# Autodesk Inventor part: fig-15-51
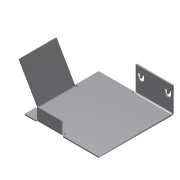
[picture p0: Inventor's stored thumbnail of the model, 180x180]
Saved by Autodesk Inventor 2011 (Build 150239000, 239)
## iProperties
Shininess: 77.0
Angle Display Precision: 2
Document Length Units: 11269
Document Angle Units: 11279
Document Time Units: 11290
Document Mass Units: 11283
Document Length Units Precision: 3
Document Angle Units Precision: 2
Created: 2002-04
Part Number: fig-15-51
Document SubType Name: Sheet Metal
Density: 1 g/cm^3
Sheet Metal Rule: Default
Density: 0.0
Volumn: 0.0
Area: 0.0
PropertySet Name: Model Information
Control State: 0
Master: False
Checked Out: False
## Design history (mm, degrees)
node "Face1"
  sketch "Sketch1"
    geometry: L1 (12.647, 25.882)-(12.647, -14.118); L2 (12.647, -14.118)-(-17.353, -14.118); L3 (-17.353, -14.118)-(-17.353, 15.882); L4 (-17.353, 15.882)-(-2.353, 15.882); L5 (-2.353, 15.882)-(-2.353, 25.882); L6 (-2.353, 25.882)-(12.647, 25.882); 1 further point
    constraints: 12 end point, 4 parallel, 1 perpendicular
    dimensions: "d5" = 30 distance of L2.end L3.end; "d6" = 10 distance of L4.end L5.end; "d7" = 15 distance of L3.end L4.end; "d25" = 15 distance of L5.end L1.start
sketch "Sketch3"
  geometry: L1 (10, -15)-(10, 0)
  constraints: 2 end point
feature "Fold3" sketch "Sketch3" dims "d26" = 0.5 (= BendRadius), "d27" = 90 deg, "d28" = 0.5 (= BendRadius), "d96" = 0.5 (= BendReliefWidth), "d97" = 0.25 (= BendReliefDepth), "d98" = 1 (= MinimumRemnant), "SeamGap" = 0.01, "Thickness" = 0.5
node "Flange2"
sketch "Sketch6"
  geometry: L1 (-6.914, 3.413)-(-5.843, 3.413); L2 (-5.843, 0.624)-(-6.914, 0.624); L3 (-6.914, 2.432)-(-5.843, 2.432); L4 (-5.843, 1.605)-(-6.914, 1.605); L5 (-6.914, 0.624)-(-6.914, 1.605); L6 (-6.914, 2.432)-(-6.914, 3.413); L7 (-6.914, 12.568)-(-6.914, 11.587); L8 (-6.914, 14.376)-(-6.914, 13.395); L9 (-6.914, 11.587)-(-5.843, 11.587); L10 (-5.843, 14.376)-(-6.914, 14.376); L11 (-6.914, 12.568)-(-5.843, 12.568); L12 (-5.843, 13.395)-(-6.914, 13.395); A1 r 1.394 centre (-5.843, 2.018) between (-5.843, 0.624) and (-5.843, 3.413); A2 r 0.413 centre (-5.843, 2.018) between (-5.843, 1.605) and (-5.843, 2.432); A3 r 1.394 centre (-5.843, 12.982) between (-5.843, 11.587) and (-5.843, 14.376); A4 r 0.413 centre (-5.843, 12.982) between (-5.843, 12.568) and (-5.843, 13.395)
  constraints: 24 end point, 8 point on circle, 4 centre point, 3 equal length, 1 perpendicular
cut "Cut1" sketch "Sketch6" dims "d49" = 0.5 (= Thickness), "d50" = 0
node "Flange3"
body "Solid1"
face "Plate1" dims "Thickness" = 0.5
sketch "Sketch5"
  geometry: L1 (20, 0)-(5, 0); L2 (5, 0)-(5, 15); L3 (5, 15)-(20, 15); L4 (20, 15)-(20, 0)
  constraints: 8 end point
face "Plate6" dims "d35" = 10, "d36" = 5, "d38" = 15, "d39" = 60 deg, "d40" = 0.5 (= BendRadius), "Thickness" = 0.5, "MinimumRemnant" = 1 (= 2 x Thickness), "BendReliefWidth" = 0.5 (= Thickness)
bend "Bend5" dims "d38" = 15, "d39" = 60 deg, "d40" = 0.5 (= BendRadius), "d99" = 0.5 (= BendReliefWidth), "d100" = 0.25 (= BendReliefDepth), "d101" = 1 (= MinimumRemnant), "SeamGap" = 0.01, "Thickness" = 0.5, "MinimumRemnant" = 1 (= 2 x Thickness), "BendReliefWidth" = 0.5 (= Thickness), "TransitionRadius" = 0.5 (= BendRadius)
sketch "Sketch7"
  geometry: L1 (25, 0)-(15, 0); L2 (15, 0)-(15, 5); L3 (15, 5)-(25, 5); L4 (25, 5)-(25, 0)
  constraints: 8 end point
face "Plate7" dims "d57" = 5, "d58" = 10, "d60" = 5, "d61" = 90 deg, "d62" = 0.5 (= BendRadius), "Thickness" = 0.5, "MinimumRemnant" = 1 (= 2 x Thickness), "BendReliefWidth" = 0.5 (= Thickness)
bend "Bend7" dims "d59" = 0.5 (= BendRadius), "d60" = 5, "d61" = 90 deg, "d62" = 0.5 (= BendRadius), "d102" = 0.5 (= BendReliefWidth), "d103" = 0.25 (= BendReliefDepth), "d104" = 1 (= MinimumRemnant), "SeamGap" = 0.01, "Thickness" = 0.5, "MinimumRemnant" = 1 (= 2 x Thickness), "BendReliefWidth" = 0.5 (= Thickness)
other parameters: "BendRadius" = 0.5 (= Thickness), "BendReliefDepth" = 0.25 (= 0.5 x Thickness), "CornerReliefSize" = 2 (= 4 x Thickness), "d0" = 0.5 (= BendRadius), "d13" = 0.5 (= BendRadius), "d31" = 0.5 (= BendRadius), "d37" = 0.5 (= BendRadius), "JacobiRadiusSize" = 0.5 (= Thickness), "GapSize" = 0.5 (= Thickness)
